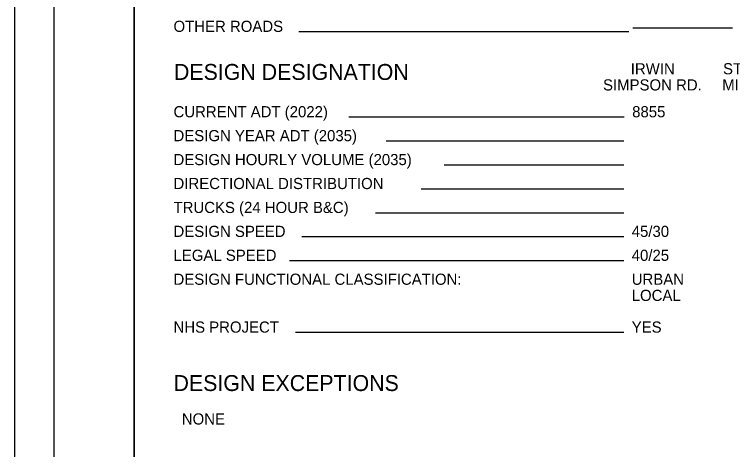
# Model space of a CAD drawing. Extents: x 0 to 34, y -4 to 22.
# Drawn here: x 0 to 9, y 5.64 to 11.1 of the extents above; entities that cross this region are included whole.
import ezdxf

# ---------------------------------------------------------------- set-up
doc = ezdxf.new("R2010")
doc.units = 0
for name, color, linetype in [('Default', 7, 'Continuous'), ('SH_Border', 7, 'Continuous'), ('SH_Cut_Line', 7, 'Continuous'), ('SH_Data', 7, 'Continuous'), ('SH_Text', 7, 'Continuous')]:
    doc.layers.add(name, color=color, linetype=linetype)

msp = doc.modelspace()

# ---------------------------------------------------------------- linework, layer by layer
at = {"layer": 'SH_Border'}
for points in [[(0.5, 21.5), (1.5, 21.5), (1.5, 0.5), (0.5, 0.5)], [(1.5, 21.5), (33.5, 21.5), (33.5, 0.5), (1.5, 0.5)]]:
    msp.add_lwpolyline(points, close=True, dxfattribs=at)
at = {"layer": 'SH_Cut_Line'}
msp.add_lwpolyline([(0, 0), (34, 0), (34, 22), (0, 22)], close=True, dxfattribs=at)
at = {"layer": 'SH_Data'}
for p, q in [((9, 10.9223), (7.75, 10.9223)), ((7.7, 10.8767), (3.5657, 10.8767)), ((7.6424, 9.8062), (4.1936, 9.8062)), ((7.6368, 9.5062), (4.6592, 9.5062)), ((7.6368, 9.2062), (5.3852, 9.2062)), ((7.6368, 8.9062), (5.0988, 8.9062)), ((7.6368, 8.6062), (4.5259, 8.6062)), ((7.6368, 8.3062), (3.6035, 8.3062)), ((7.6368, 8.0062), (3.4488, 8.0062)), ((7.6368, 7.1062), (3.5243, 7.1062))]:
    msp.add_line(p, q, dxfattribs=at)

# ---------------------------------------------------------------- texts
at = {"layer": 'Default'}
for s, p in [('IRWIN', (7.725, 10.3448)), ('STUBBS', (8.881, 10.3448)), ('SIMPSON RD.', (7.3772, 10.1423)), ('MILL RD.', (8.8713, 10.1423))]:
    msp.add_text(s, height=0.14, dxfattribs=at).set_placement(p)
at = {"layer": 'SH_Data'}
msp.add_text('DESIGN DESIGNATION', height=0.2, dxfattribs=at).set_placement((2, 10.2747))
at = {"layer": 'SH_Text'}
for s, height, p in [('OTHER ROADS', 0.14, (1.9944, 10.8767)), ('CURRENT ADT (2022)', 0.14, (1.9944, 9.8062)), ('8855  ', 0.14, (7.7424, 9.8062)), ('DESIGN YEAR ADT (2035)', 0.14, (1.9944, 9.5062)), ('DESIGN HOURLY VOLUME (2035)', 0.14, (1.9944, 9.2062)), ('DIRECTIONAL DISTRIBUTION', 0.14, (1.9944, 8.9062)), ('TRUCKS (24 HOUR B&C)', 0.14, (1.9944, 8.6062)), ('DESIGN SPEED', 0.14, (1.9944, 8.3062)), ('45/30 ', 0.14, (7.7368, 8.3062)), ('LEGAL SPEED', 0.14, (1.9944, 8.0062)), ('40/25 ', 0.14, (7.7368, 8.0062)), ('DESIGN FUNCTIONAL CLASSIFICATION:', 0.14, (1.9944, 7.7062)), ('URBAN', 0.14, (7.7368, 7.7062)), ('LOCAL', 0.14, (7.7368, 7.5037)), ('NHS PROJECT', 0.14, (1.9944, 7.1062)), ('YES   ', 0.14, (7.7368, 7.1062)), ('DESIGN EXCEPTIONS', 0.2, (1.9944, 6.3744)), ('  NONE                                   ', 0.14, (1.9944, 5.9544))]:
    msp.add_text(s, height=height, dxfattribs=at).set_placement(p)

doc.saveas('drawing.dxf')
